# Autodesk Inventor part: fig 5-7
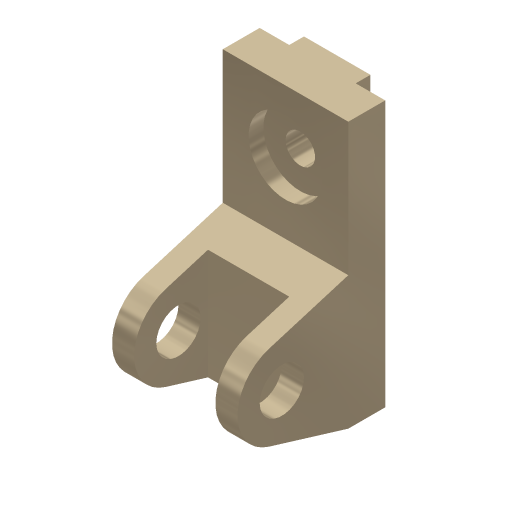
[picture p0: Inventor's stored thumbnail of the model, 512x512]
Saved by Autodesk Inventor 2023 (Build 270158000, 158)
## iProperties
Created: 2001-11
Part Number: fig 5-7
Document SubType Name: Modeling
Designer: Renu Muthoo
Density: 1 g/cm^3
Material: Generic
Appearance: Metal-Titanium (Polished)
Control State: 0
Master: False
Checked Out: False
Shininess: 65.0
Angle Display Precision: 2
Document Length Units: 11269
Document Angle Units: 11279
Document Time Units: 11290
Document Mass Units: 11283
Document Length Units Precision: 3
Document Angle Units Precision: 2
Compacted: False
Density: 0.0
Volumn: 0.0
Area: 0.0
PropertySet Name: Model Information
Author: Renu Muthoo
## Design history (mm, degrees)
node "Sketch1"
sketch "Sketch2"
  geometry: L1 (33.257, 104.664)-(33.257, -75.336); L2 (33.257, -75.336)-(8.257, -75.336); L3 (8.257, -75.336)-(-45.451, -59.045); L4 (-45.451, -1.628)-(8.257, 14.664); L5 (8.257, 14.664)-(8.257, 104.664); L6 (8.257, 104.664)-(33.257, 104.664); C1 r 15 at (-36.743, -30.336); A1 r 30 centre (-36.743, -30.336) between (-45.451, -1.628) and (-45.451, -59.045)
  constraints: 12 end point, 2 centre point, 2 equal length, 2 parallel, 2 point on circle, 2 tangent, 1 coincident, 1 perpendicular, 1 vertical
  dimensions: "d0" = 180 distance of L1.start L1.end; "d1" = 30 radius of A1; "d2" = 25 distance of L5.end L1.start; "d3" = 45 distance from line of L2 A1.centre; "d4" = 70 distance from line of L1 A1.centre; "d5" = 30 diameter of C1
extrude "Extrusion1" new body sketch "Sketch2" distance "d6" = 85; taper "d7" = 0 deg
workplane "Work Plane1"
sketch "Sketch3"
  geometry: L1 (15, 62.364)-(70, 62.364); L2 (70, 62.364)-(70, -52.386); L3 (70, -52.386)-(15, -52.386); L4 (15, -52.386)-(15, 62.364); L5 (0, -45)-(0, -28.708) reference
  constraints: 8 end point, 2 parallel, 1 horizontal, 1 perpendicular
  dimensions: "d8" = 55 distance of L1.start L1.end; "d9" = 15 distance between parallel lines of L5 L4
extrude "Extrusion2" cut sketch "Sketch3" distance "d10" = 50; taper "d11" = 0 deg
sketch "Sketch4"
  geometry: L1 (0, 25)-(85, 25) reference; L2 (0, 0)-(0, 25) reference; L3 (20, 25)-(65, 25); L4 (65, 25)-(65, 35); L5 (65, 35)-(20, 35); L6 (20, 35)-(20, 25)
  constraints: 8 end point, 2 parallel, 1 horizontal, 1 perpendicular, 1 point on line
  dimensions: "d12" = 45 distance of L4.end L5.end; "d13" = 10 distance of L3.end L4.end; "d14" = 20 distance between parallel lines of L2 L6
extrude "Extrusion3" join sketch "Sketch4" stored distance "d15" = 50; taper "d16" = 0 deg
sketch "Sketch5"
  geometry: L1 (85, 0)-(85, 90) reference; L2 (0, 90)-(85, 90) reference; 1 further point
  dimensions: "d17" = 42 distance from line of L2 point (42.5, 48); "d18" = 42.5 distance from line of L1 point (42.5, 48)
hole "Hole1" sketch "Sketch5" at (42.5, 48) diameter "d19" = 20; stored, may be unused: countersink angle "d23" = 82 deg, drill point angle "d25" = 118 deg; dims "d20" = 6, "d21" = 50, "d22" = 10, "d24" = 8
body "Solid1"
